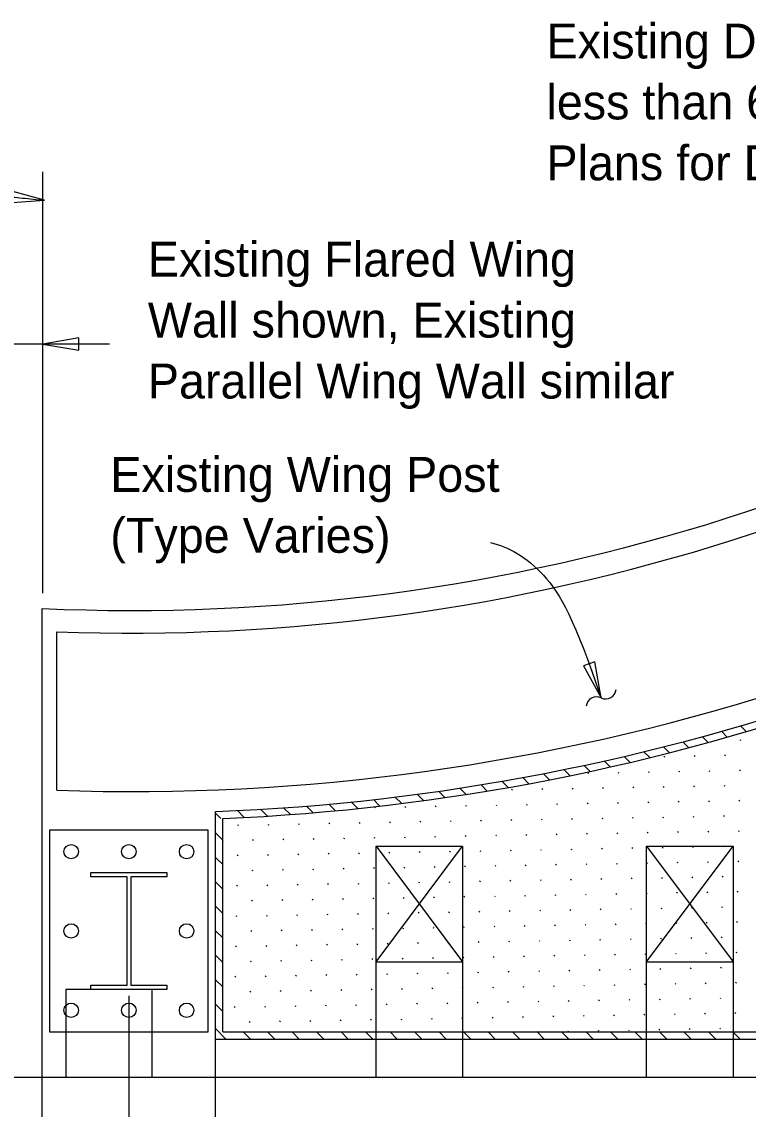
# Model space of a CAD drawing. Extents: x 21526.6 to 21598.7, y 56118.1 to 56155.9.
# Drawn here: x 21554.18 to 21558.38, y 56146.83 to 56153.11 of the extents above; entities that cross this region are included whole.
import ezdxf

# ---------------------------------------------------------------- set-up
doc = ezdxf.new("R2010")
doc.units = 0
for name, color, linetype in [('AdhocPoint_dp', 7, 'Continuous'), ('Patterning', 7, 'Continuous'), ('PlotBorder_dp', 7, 'Continuous'), ('SheetBorder_dp', 7, 'Continuous')]:
    doc.layers.add(name, color=color, linetype=linetype)

msp = doc.modelspace()

# ---------------------------------------------------------------- linework, layer by layer
at = {"layer": 'AdhocPoint_dp'}
for p, q in [((21554.3018, 56145.2536), (21554.3018, 56149.7195)), ((21554.3851, 56148.6691), (21554.3851, 56149.5851)), ((21555.3018, 56145.2536), (21555.3018, 56148.546)), ((21555.3435, 56147.2732), (21555.3435, 56148.506)), ((21555.3435, 56147.2732), (21562.4118, 56147.2732)), ((21555.3018, 56147.2315), (21562.4118, 56147.2315))]:
    msp.add_line(p, q, dxfattribs=at)
for radius, start, end in [(11.3394, 267.40102, 307.93264), (11.4702, 267.84731, 307.49092), (12.3856, 268.00648, 307.27295), (12.5106, 272.22541, 307.24718), (12.5523, 272.40859, 307.2387)]:
    msp.add_arc((21554.816, 56161.0472), radius, start, end, dxfattribs=at)
at = {"layer": 'Patterning'}
for p, q in [((21558.3332, 56149.0412), (21558.3668, 56149.0077)), ((21558.0013, 56148.9489), (21558.0349, 56148.9152)), ((21558.1128, 56148.9788), (21558.1467, 56148.9449)), ((21558.2234, 56149.0096), (21558.2568, 56148.9763)), ((21558.3327, 56148.9567), (21558.336, 56148.9623)), ((21557.7756, 56148.8917), (21557.8096, 56148.8577)), ((21557.8889, 56148.9199), (21557.9231, 56148.8856)), ((21557.5463, 56148.8382), (21557.5808, 56148.8037)), ((21557.6614, 56148.8645), (21557.696, 56148.8299)), ((21557.8928, 56148.8609), (21557.8961, 56148.8665)), ((21558.0681, 56148.8642), (21558.0714, 56148.8698)), ((21558.2435, 56148.8674), (21558.2467, 56148.873)), ((21557.1953, 56148.7649), (21557.2306, 56148.7296)), ((21557.3133, 56148.7884), (21557.3481, 56148.7535)), ((21557.4303, 56148.8128), (21557.4652, 56148.7778)), ((21557.453, 56148.7652), (21557.4562, 56148.7708)), ((21557.6283, 56148.7684), (21557.6315, 56148.774)), ((21557.8036, 56148.7717), (21557.8068, 56148.7773)), ((21557.9789, 56148.7749), (21557.9821, 56148.7805)), ((21558.1542, 56148.7782), (21558.1574, 56148.7838)), ((21558.3295, 56148.7814), (21558.3327, 56148.787)), ((21556.8353, 56148.7007), (21556.8712, 56148.6648)), ((21556.9563, 56148.7211), (21556.9921, 56148.6853)), ((21557.0763, 56148.7425), (21557.1117, 56148.7071)), ((21558.2402, 56148.6921), (21558.2435, 56148.6977)), ((21556.4658, 56148.6459), (21556.5025, 56148.6092)), ((21556.5901, 56148.663), (21556.6266, 56148.6265)), ((21556.7132, 56148.6813), (21556.7494, 56148.6451)), ((21557.0131, 56148.6694), (21557.0163, 56148.675)), ((21557.1884, 56148.6727), (21557.1916, 56148.6783)), ((21557.3637, 56148.6759), (21557.3669, 56148.6815)), ((21557.539, 56148.6792), (21557.5422, 56148.6848)), ((21557.7143, 56148.6824), (21557.7175, 56148.688)), ((21557.8896, 56148.6856), (21557.8928, 56148.6912)), ((21558.0649, 56148.6889), (21558.0681, 56148.6945)), ((21555.8271, 56148.5775), (21555.8654, 56148.5392)), ((21555.9572, 56148.5888), (21555.9951, 56148.5509)), ((21556.0862, 56148.6013), (21556.1241, 56148.5633)), ((21556.2139, 56148.615), (21556.2511, 56148.5778)), ((21556.2226, 56148.5672), (21556.2258, 56148.5728)), ((21556.3404, 56148.6298), (21556.3776, 56148.5926)), ((21556.3979, 56148.5704), (21556.4011, 56148.576)), ((21556.5732, 56148.5737), (21556.5764, 56148.5793)), ((21556.7485, 56148.5769), (21556.7518, 56148.5825)), ((21556.9238, 56148.5802), (21556.9271, 56148.5858)), ((21557.0991, 56148.5834), (21557.1024, 56148.589)), ((21557.2744, 56148.5866), (21557.2777, 56148.5922)), ((21557.4497, 56148.5899), (21557.453, 56148.5955)), ((21557.625, 56148.5931), (21557.6283, 56148.5987)), ((21557.8003, 56148.5964), (21557.8036, 56148.602)), ((21557.9756, 56148.5996), (21557.9789, 56148.6052)), ((21558.1509, 56148.6029), (21558.1542, 56148.6084)), ((21558.3262, 56148.6061), (21558.3295, 56148.6117)), ((21555.3018, 56148.5371), (21555.3328, 56148.5061)), ((21555.4287, 56148.5516), (21555.4682, 56148.5121)), ((21555.5628, 56148.5589), (21555.6017, 56148.52)), ((21555.6956, 56148.5676), (21555.7342, 56148.529)), ((21557.5358, 56148.5039), (21557.539, 56148.5095)), ((21557.7111, 56148.5071), (21557.7143, 56148.5127)), ((21557.8864, 56148.5103), (21557.8896, 56148.5159)), ((21558.0617, 56148.5136), (21558.0649, 56148.5192)), ((21558.237, 56148.5168), (21558.2402, 56148.5224)), ((21555.4321, 56148.465), (21555.4354, 56148.4706)), ((21555.6074, 56148.4682), (21555.6107, 56148.4738)), ((21555.7827, 56148.4714), (21555.786, 56148.477)), ((21555.958, 56148.4747), (21555.9613, 56148.4803)), ((21556.1333, 56148.4779), (21556.1366, 56148.4835)), ((21556.3086, 56148.4812), (21556.3119, 56148.4868)), ((21556.4839, 56148.4844), (21556.4872, 56148.49)), ((21556.6592, 56148.4877), (21556.6625, 56148.4933)), ((21556.8345, 56148.4909), (21556.8378, 56148.4965)), ((21557.0098, 56148.4941), (21557.0131, 56148.4997)), ((21557.1851, 56148.4974), (21557.1884, 56148.503)), ((21557.3605, 56148.5006), (21557.3637, 56148.5062)), ((21555.3018, 56148.4229), (21555.3435, 56148.3812)), ((21555.5181, 56148.3789), (21555.5214, 56148.3845)), ((21555.6934, 56148.3822), (21555.6967, 56148.3878)), ((21555.8688, 56148.3854), (21555.872, 56148.391)), ((21556.0441, 56148.3887), (21556.0473, 56148.3943)), ((21556.2194, 56148.3919), (21556.2226, 56148.3975)), ((21556.3947, 56148.3951), (21556.3979, 56148.4007)), ((21556.57, 56148.3984), (21556.5732, 56148.404)), ((21556.7453, 56148.4016), (21556.7485, 56148.4072)), ((21556.9206, 56148.4049), (21556.9238, 56148.4105)), ((21557.0959, 56148.4081), (21557.0991, 56148.4137)), ((21557.2712, 56148.4113), (21557.2744, 56148.4169)), ((21557.4465, 56148.4146), (21557.4497, 56148.4202)), ((21557.6218, 56148.4178), (21557.625, 56148.4234)), ((21557.7971, 56148.4211), (21557.8003, 56148.4267)), ((21557.9724, 56148.4243), (21557.9756, 56148.4299)), ((21558.1477, 56148.4275), (21558.1509, 56148.4331)), ((21558.323, 56148.4308), (21558.3262, 56148.4364)), ((21555.3435, 56148.3768), (21555.3461, 56148.3813)), ((21556.2289, 56147.012), (21556.2289, 56148.3453)), ((21556.2289, 56148.3453), (21556.7289, 56148.3453)), ((21556.2289, 56148.3453), (21556.7289, 56147.6786)), ((21556.2289, 56147.6786), (21556.7289, 56148.3453)), ((21556.7289, 56148.3453), (21556.7289, 56147.012)), ((21556.8313, 56148.3156), (21556.8345, 56148.3212)), ((21557.0066, 56148.3188), (21557.0098, 56148.3244)), ((21557.1819, 56148.3221), (21557.1851, 56148.3277)), ((21557.3572, 56148.3253), (21557.3605, 56148.3309)), ((21557.5325, 56148.3286), (21557.5358, 56148.3342)), ((21557.7078, 56148.3318), (21557.7111, 56148.3374)), ((21557.7914, 56147.012), (21557.7914, 56148.3453)), ((21557.7914, 56148.3453), (21558.2914, 56148.3453)), ((21557.7914, 56148.3453), (21558.2914, 56147.6786)), ((21557.7914, 56147.6786), (21558.2914, 56148.3453)), ((21557.8831, 56148.335), (21557.8864, 56148.3406)), ((21558.0584, 56148.3383), (21558.0617, 56148.3439)), ((21558.2337, 56148.3415), (21558.237, 56148.3471)), ((21558.2914, 56148.3453), (21558.2914, 56147.012)), ((21555.3018, 56148.2814), (21555.3435, 56148.2397)), ((21555.4289, 56148.2897), (21555.4321, 56148.2953)), ((21555.6042, 56148.2929), (21555.6074, 56148.2985)), ((21555.7795, 56148.2961), (21555.7827, 56148.3017)), ((21555.9548, 56148.2994), (21555.958, 56148.305)), ((21556.1301, 56148.3026), (21556.1333, 56148.3082)), ((21556.3054, 56148.3059), (21556.3086, 56148.3115)), ((21556.4807, 56148.3091), (21556.4839, 56148.3147)), ((21556.656, 56148.3123), (21556.6592, 56148.3179)), ((21558.1445, 56148.2522), (21558.1477, 56148.2578)), ((21558.3198, 56148.2555), (21558.323, 56148.2611)), ((21555.5149, 56148.2036), (21555.5181, 56148.2092)), ((21555.6902, 56148.2069), (21555.6934, 56148.2125)), ((21555.8655, 56148.2101), (21555.8688, 56148.2157)), ((21556.0408, 56148.2134), (21556.0441, 56148.219)), ((21556.2161, 56148.2166), (21556.2194, 56148.2222)), ((21556.3914, 56148.2198), (21556.3947, 56148.2254)), ((21556.5667, 56148.2231), (21556.57, 56148.2287)), ((21556.742, 56148.2263), (21556.7453, 56148.2319)), ((21556.9173, 56148.2296), (21556.9206, 56148.2352)), ((21557.0926, 56148.2328), (21557.0959, 56148.2384)), ((21557.2679, 56148.236), (21557.2712, 56148.2416)), ((21557.4432, 56148.2393), (21557.4465, 56148.2449)), ((21557.6185, 56148.2425), (21557.6218, 56148.2481)), ((21557.7939, 56148.2458), (21557.7971, 56148.2514)), ((21557.9692, 56148.249), (21557.9724, 56148.2546)), ((21555.3018, 56148.14), (21555.3435, 56148.0983)), ((21556.1268, 56148.1273), (21556.1301, 56148.1329)), ((21556.3021, 56148.1306), (21556.3054, 56148.1362)), ((21556.4775, 56148.1338), (21556.4807, 56148.1394)), ((21556.6528, 56148.137), (21556.656, 56148.1426)), ((21556.8281, 56148.1403), (21556.8313, 56148.1459)), ((21557.0034, 56148.1435), (21557.0066, 56148.1491)), ((21557.1787, 56148.1468), (21557.1819, 56148.1524)), ((21557.354, 56148.15), (21557.3572, 56148.1556)), ((21557.5293, 56148.1532), (21557.5325, 56148.1588)), ((21557.7046, 56148.1565), (21557.7078, 56148.1621)), ((21557.8799, 56148.1597), (21557.8831, 56148.1653)), ((21558.0552, 56148.163), (21558.0584, 56148.1686)), ((21558.2305, 56148.1662), (21558.2337, 56148.1718)), ((21555.4256, 56148.1144), (21555.4289, 56148.12)), ((21555.6009, 56148.1176), (21555.6042, 56148.1232)), ((21555.7762, 56148.1208), (21555.7795, 56148.1264)), ((21555.9515, 56148.1241), (21555.9548, 56148.1297)), ((21557.44, 56148.064), (21557.4432, 56148.0696)), ((21557.6153, 56148.0672), (21557.6185, 56148.0728)), ((21557.7906, 56148.0705), (21557.7939, 56148.0761)), ((21557.9659, 56148.0737), (21557.9692, 56148.0793)), ((21558.1412, 56148.0769), (21558.1445, 56148.0825)), ((21558.3165, 56148.0802), (21558.3198, 56148.0858)), ((21555.5117, 56148.0283), (21555.5149, 56148.0339)), ((21555.687, 56148.0316), (21555.6902, 56148.0372)), ((21555.8623, 56148.0348), (21555.8655, 56148.0404)), ((21556.0376, 56148.0381), (21556.0408, 56148.0436)), ((21556.2129, 56148.0413), (21556.2161, 56148.0469)), ((21556.3882, 56148.0445), (21556.3914, 56148.0501)), ((21556.5635, 56148.0478), (21556.5667, 56148.0534)), ((21556.7388, 56148.051), (21556.742, 56148.0566)), ((21556.9141, 56148.0543), (21556.9173, 56148.0599)), ((21557.0894, 56148.0575), (21557.0926, 56148.0631)), ((21557.2647, 56148.0607), (21557.2679, 56148.0663)), ((21555.3018, 56147.9986), (21555.3435, 56147.9569)), ((21555.4224, 56147.9391), (21555.4256, 56147.9447)), ((21555.5977, 56147.9423), (21555.6009, 56147.9479)), ((21555.773, 56147.9455), (21555.7762, 56147.9511)), ((21555.9483, 56147.9488), (21555.9515, 56147.9544)), ((21556.1236, 56147.952), (21556.1268, 56147.9576)), ((21556.2989, 56147.9553), (21556.3021, 56147.9609)), ((21556.4742, 56147.9585), (21556.4775, 56147.9641)), ((21556.6495, 56147.9617), (21556.6528, 56147.9673)), ((21556.8248, 56147.965), (21556.8281, 56147.9706)), ((21557.0001, 56147.9682), (21557.0034, 56147.9738)), ((21557.1754, 56147.9715), (21557.1787, 56147.9771)), ((21557.3507, 56147.9747), (21557.354, 56147.9803)), ((21557.526, 56147.9779), (21557.5293, 56147.9835)), ((21557.7013, 56147.9812), (21557.7046, 56147.9868)), ((21557.8766, 56147.9844), (21557.8799, 56147.99)), ((21558.0519, 56147.9877), (21558.0552, 56147.9933)), ((21558.2272, 56147.9909), (21558.2305, 56147.9965)), ((21556.7355, 56147.8757), (21556.7388, 56147.8813)), ((21556.9109, 56147.879), (21556.9141, 56147.8845)), ((21557.0862, 56147.8822), (21557.0894, 56147.8878)), ((21557.2615, 56147.8854), (21557.2647, 56147.891)), ((21557.4368, 56147.8887), (21557.44, 56147.8943)), ((21557.6121, 56147.8919), (21557.6153, 56147.8975)), ((21557.7874, 56147.8952), (21557.7906, 56147.9008)), ((21557.9627, 56147.8984), (21557.9659, 56147.904)), ((21558.138, 56147.9016), (21558.1412, 56147.9072)), ((21558.3133, 56147.9049), (21558.3165, 56147.9105)), ((21555.3018, 56147.8572), (21555.3435, 56147.8155)), ((21555.5084, 56147.853), (21555.5117, 56147.8586)), ((21555.6837, 56147.8563), (21555.687, 56147.8619)), ((21555.859, 56147.8595), (21555.8623, 56147.8651)), ((21556.0343, 56147.8627), (21556.0376, 56147.8683)), ((21556.2096, 56147.866), (21556.2129, 56147.8716)), ((21556.3849, 56147.8692), (21556.3882, 56147.8748)), ((21556.5602, 56147.8725), (21556.5635, 56147.8781)), ((21558.0487, 56147.8124), (21558.0519, 56147.818)), ((21558.224, 56147.8156), (21558.2272, 56147.8212)), ((21555.4191, 56147.7638), (21555.4224, 56147.7693)), ((21555.5945, 56147.767), (21555.5977, 56147.7726)), ((21555.7698, 56147.7702), (21555.773, 56147.7758)), ((21555.9451, 56147.7735), (21555.9483, 56147.7791)), ((21556.1204, 56147.7767), (21556.1236, 56147.7823)), ((21556.2957, 56147.78), (21556.2989, 56147.7856)), ((21556.471, 56147.7832), (21556.4742, 56147.7888)), ((21556.6463, 56147.7864), (21556.6495, 56147.792)), ((21556.8216, 56147.7897), (21556.8248, 56147.7953)), ((21556.9969, 56147.7929), (21557.0001, 56147.7985)), ((21557.1722, 56147.7962), (21557.1754, 56147.8018)), ((21557.3475, 56147.7994), (21557.3507, 56147.805)), ((21557.5228, 56147.8026), (21557.526, 56147.8082)), ((21557.6981, 56147.8059), (21557.7013, 56147.8115)), ((21557.8734, 56147.8091), (21557.8766, 56147.8147)), ((21555.3018, 56147.7157), (21555.3435, 56147.674)), ((21556.0311, 56147.6874), (21556.0343, 56147.693)), ((21556.2064, 56147.6907), (21556.2096, 56147.6963)), ((21556.3817, 56147.6939), (21556.3849, 56147.6995)), ((21556.557, 56147.6972), (21556.5602, 56147.7028)), ((21556.7323, 56147.7004), (21556.7355, 56147.706)), ((21556.9076, 56147.7036), (21556.9109, 56147.7092)), ((21557.0829, 56147.7069), (21557.0862, 56147.7125)), ((21557.2582, 56147.7101), (21557.2615, 56147.7157)), ((21557.4335, 56147.7134), (21557.4368, 56147.719)), ((21557.6088, 56147.7166), (21557.6121, 56147.7222)), ((21557.7841, 56147.7199), (21557.7874, 56147.7255)), ((21557.9594, 56147.7231), (21557.9627, 56147.7287)), ((21558.1347, 56147.7263), (21558.138, 56147.7319)), ((21558.31, 56147.7296), (21558.3133, 56147.7352)), ((21555.5052, 56147.6777), (21555.5084, 56147.6833)), ((21555.6805, 56147.681), (21555.6837, 56147.6866)), ((21555.8558, 56147.6842), (21555.859, 56147.6898)), ((21556.2289, 56147.6786), (21556.7289, 56147.6786)), ((21557.3442, 56147.6241), (21557.3475, 56147.6297)), ((21557.5196, 56147.6273), (21557.5228, 56147.6329)), ((21557.6949, 56147.6306), (21557.6981, 56147.6362)), ((21557.7914, 56147.6786), (21558.2914, 56147.6786)), ((21557.8702, 56147.6338), (21557.8734, 56147.6394)), ((21558.0455, 56147.6371), (21558.0487, 56147.6427)), ((21558.2208, 56147.6403), (21558.224, 56147.6459)), ((21555.3018, 56147.5743), (21555.3435, 56147.5326)), ((21555.4159, 56147.5884), (21555.4191, 56147.594)), ((21555.5912, 56147.5917), (21555.5945, 56147.5973)), ((21555.7665, 56147.5949), (21555.7698, 56147.6005)), ((21555.9418, 56147.5982), (21555.9451, 56147.6038)), ((21556.1171, 56147.6014), (21556.1204, 56147.607)), ((21556.2924, 56147.6047), (21556.2957, 56147.6103)), ((21556.4677, 56147.6079), (21556.471, 56147.6135)), ((21556.643, 56147.6111), (21556.6463, 56147.6167)), ((21556.8183, 56147.6144), (21556.8216, 56147.62)), ((21556.9936, 56147.6176), (21556.9969, 56147.6232)), ((21557.1689, 56147.6209), (21557.1722, 56147.6265)), ((21554.9372, 56147.5174), (21554.4372, 56147.5174)), ((21554.4372, 56147.5174), (21554.4372, 56147.012)), ((21554.9372, 56147.012), (21554.9372, 56147.5174)), ((21555.5019, 56147.5024), (21555.5052, 56147.508)), ((21555.6772, 56147.5057), (21555.6805, 56147.5113)), ((21555.8525, 56147.5089), (21555.8558, 56147.5145)), ((21556.0279, 56147.5121), (21556.0311, 56147.5177)), ((21556.2032, 56147.5154), (21556.2064, 56147.521)), ((21556.3785, 56147.5186), (21556.3817, 56147.5242)), ((21556.5538, 56147.5219), (21556.557, 56147.5275)), ((21556.7291, 56147.5251), (21556.7323, 56147.5307)), ((21556.9044, 56147.5283), (21556.9076, 56147.5339)), ((21557.0797, 56147.5316), (21557.0829, 56147.5372)), ((21557.255, 56147.5348), (21557.2582, 56147.5404)), ((21557.4303, 56147.5381), (21557.4335, 56147.5437)), ((21557.6056, 56147.5413), (21557.6088, 56147.5469)), ((21557.7809, 56147.5445), (21557.7841, 56147.5501)), ((21557.9562, 56147.5478), (21557.9594, 56147.5534)), ((21558.1315, 56147.551), (21558.1347, 56147.5566)), ((21558.3068, 56147.5543), (21558.31, 56147.5599)), ((21556.6398, 56147.4358), (21556.643, 56147.4414)), ((21556.8151, 56147.4391), (21556.8183, 56147.4447)), ((21556.9904, 56147.4423), (21556.9936, 56147.4479)), ((21557.1657, 56147.4456), (21557.1689, 56147.4512)), ((21557.341, 56147.4488), (21557.3442, 56147.4544)), ((21557.5163, 56147.452), (21557.5196, 56147.4576)), ((21557.6916, 56147.4553), (21557.6949, 56147.4609)), ((21557.8669, 56147.4585), (21557.8702, 56147.4641)), ((21558.0422, 56147.4618), (21558.0455, 56147.4674)), ((21558.2175, 56147.465), (21558.2208, 56147.4706)), ((21555.3018, 56147.4329), (21555.3435, 56147.3912)), ((21555.4127, 56147.4131), (21555.4159, 56147.4187)), ((21555.588, 56147.4164), (21555.5912, 56147.422)), ((21555.7633, 56147.4196), (21555.7665, 56147.4252)), ((21555.9386, 56147.4229), (21555.9418, 56147.4285)), ((21556.1139, 56147.4261), (21556.1171, 56147.4317)), ((21556.2892, 56147.4293), (21556.2924, 56147.4349)), ((21556.4645, 56147.4326), (21556.4677, 56147.4382)), ((21557.9529, 56147.3725), (21557.9562, 56147.3781)), ((21558.1283, 56147.3757), (21558.1315, 56147.3813)), ((21558.3036, 56147.379), (21558.3068, 56147.3846)), ((21555.4987, 56147.3271), (21555.5019, 56147.3327)), ((21555.674, 56147.3304), (21555.6772, 56147.336)), ((21555.8493, 56147.3336), (21555.8525, 56147.3392)), ((21556.0246, 56147.3368), (21556.0279, 56147.3424)), ((21556.1999, 56147.3401), (21556.2032, 56147.3457)), ((21556.3752, 56147.3433), (21556.3785, 56147.3489)), ((21556.5505, 56147.3466), (21556.5538, 56147.3522)), ((21556.7258, 56147.3498), (21556.7291, 56147.3554)), ((21556.9011, 56147.353), (21556.9044, 56147.3586)), ((21557.0764, 56147.3563), (21557.0797, 56147.3619)), ((21557.2517, 56147.3595), (21557.255, 56147.3651)), ((21557.427, 56147.3628), (21557.4303, 56147.3684)), ((21557.6023, 56147.366), (21557.6056, 56147.3716)), ((21557.7776, 56147.3692), (21557.7809, 56147.3748)), ((21555.3018, 56147.2915), (21555.3617, 56147.2315)), ((21555.4615, 56147.2732), (21555.5032, 56147.2315)), ((21555.6029, 56147.2732), (21555.6446, 56147.2315)), ((21555.7443, 56147.2732), (21555.786, 56147.2315)), ((21555.8857, 56147.2732), (21555.9274, 56147.2315)), ((21556.0272, 56147.2732), (21556.0689, 56147.2315)), ((21556.1686, 56147.2732), (21556.2103, 56147.2315)), ((21556.31, 56147.2732), (21556.3517, 56147.2315)), ((21556.4514, 56147.2732), (21556.4931, 56147.2315)), ((21556.5928, 56147.2732), (21556.6345, 56147.2315)), ((21556.7343, 56147.2732), (21556.776, 56147.2315)), ((21556.8757, 56147.2732), (21556.9174, 56147.2315)), ((21557.0171, 56147.2732), (21557.0588, 56147.2315)), ((21557.1585, 56147.2732), (21557.2002, 56147.2315)), ((21557.1642, 56147.2732), (21557.1657, 56147.2758)), ((21557.2999, 56147.2732), (21557.3416, 56147.2315)), ((21557.3378, 56147.2735), (21557.341, 56147.2791)), ((21557.4414, 56147.2732), (21557.4831, 56147.2315)), ((21557.5131, 56147.2767), (21557.5163, 56147.2823)), ((21557.5828, 56147.2732), (21557.6245, 56147.2315)), ((21557.6884, 56147.28), (21557.6916, 56147.2856)), ((21557.7242, 56147.2732), (21557.7659, 56147.2315)), ((21557.8637, 56147.2832), (21557.8669, 56147.2888)), ((21557.8656, 56147.2732), (21557.9073, 56147.2315)), ((21558.0071, 56147.2732), (21558.0488, 56147.2315)), ((21558.039, 56147.2865), (21558.0422, 56147.2921)), ((21558.1485, 56147.2732), (21558.1902, 56147.2315)), ((21558.2143, 56147.2897), (21558.2175, 56147.2953)), ((21558.2899, 56147.2732), (21558.3316, 56147.2315))]:
    msp.add_line(p, q, dxfattribs=at)
at = {"layer": 'PlotBorder_dp'}
for p, q in [((21554.3043, 56149.8081), (21554.3043, 56152.2434)), ((21554.6897, 56151.2476), (21550.7812, 56151.2476)), ((21554.8018, 56147.4803), (21554.8018, 56143.8094))]:
    msp.add_line(p, q, dxfattribs=at)
for points in [[(21554.3137, 56152.0784), (21554.11, 56152.1343), (21554.103, 56152.0641)], [(21554.3043, 56151.2476), (21554.5126, 56151.2123), (21554.5126, 56151.2828)], [(21557.5282, 56149.2027), (21557.4931, 56149.4109), (21557.4264, 56149.3877)]]:
    msp.add_lwpolyline(points, close=True, dxfattribs=at)
for centre, start, end in [((21557.5022, 56149.1497), 63.37602, 175.10324), ((21557.5556, 56149.2563), 243.37602, 355.10324)]:
    msp.add_arc(centre, 0.0596, start, end, dxfattribs=at)
for points, degree in [([(21553.1921, 56152.3226), (21553.3769, 56152.316), (21553.6144, 56152.217), (21553.6474, 56152.1576), (21553.9178, 56152.118), (21554.3137, 56152.0784)], 2), ([(21556.8894, 56150.0999), (21556.9902, 56150.0761), (21557.2075, 56149.9599), (21557.3787, 56149.6515), (21557.5282, 56149.2027)], 3)]:
    msp.add_open_spline(points, degree=degree, dxfattribs=at)
at = {"layer": 'SheetBorder_dp'}
msp.add_line((21552.8484, 56147.012), (21566.3956, 56147.012), dxfattribs=at)
msp.add_lwpolyline([(21554.3435, 56147.2726), (21555.2601, 56147.2726), (21555.2601, 56148.4393), (21554.3435, 56148.4393)], close=True, dxfattribs=at)
msp.add_lwpolyline([(21555.0205, 56147.5174), (21554.583, 56147.5174), (21554.583, 56147.5435), (21554.7914, 56147.5435), (21554.7914, 56148.1685), (21554.583, 56148.1685), (21554.583, 56148.1945), (21555.0205, 56148.1945), (21555.0205, 56148.1685), (21554.8122, 56148.1685), (21554.8122, 56147.5435), (21555.0205, 56147.5435), (21555.0205, 56147.5174)], dxfattribs=at)
for centre in [(21554.4685, 56148.3143), (21554.8018, 56148.3143), (21555.1351, 56148.3143), (21554.4685, 56147.856), (21555.1351, 56147.856), (21554.4685, 56147.3976), (21554.8018, 56147.3976), (21555.1351, 56147.3976)]:
    msp.add_circle(centre, 0.0417, dxfattribs=at)

# ---------------------------------------------------------------- texts
at = {"layer": 'PlotBorder_dp'}
for s, p in [('Existing Detached Sidewalk or Integral Sidewalk ', (21557.213, 56152.8975)), ('less than 6" thick to be removed.  See Roadway ', (21557.213, 56152.5455)), ('Plans for Details of Sidewalk replacement.', (21557.213, 56152.1935)), ('Existing Flared Wing ', (21554.9114, 56151.637)), ('Wall shown, Existing ', (21554.9114, 56151.285)), ('Parallel Wing Wall similar', (21554.9114, 56150.933)), ('Existing Wing Post ', (21554.6947, 56150.3933)), ('(Type Varies)', (21554.6947, 56150.0413))]:
    msp.add_text(s, height=0.2016, dxfattribs=at).set_placement(p)

doc.saveas('drawing.dxf')
